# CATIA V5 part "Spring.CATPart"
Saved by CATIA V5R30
Part number: Part1
Bounding box of the stored display mesh (mm): x -50 to 50, y -44.999 to 44.983, z -4.984 to 154.984
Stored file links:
  D:\PROJECTS\CATIA V56R 2020\Resources\Tutorial Files\c19_catia_v5_6r2019_tut\C19_tut_01.CATPart\Spring.CATPart
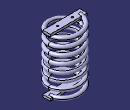
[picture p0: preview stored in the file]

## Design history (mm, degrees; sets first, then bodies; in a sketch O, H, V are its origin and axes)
Body1 (main body)
  Point1: (0, 0, 0)
  Point2: (0, 0, 150)
  Line1: type PtPt, FirstPoint Point2, SecondPoint Point1
  Point3: (40, 0, 0)
  Helix1: Direction Line1, RefPoint Point3, Pitch 20, Height 150, TaperAngle 0, Revolutions 1
  Plane1: type Normal, Curve Helix1, RefPoint vertex of Helix1, Ratio 0
  Sketch1 on Plane1, origin (0, -11.8615, 0.9439), H (1, 0, 0), V (0, 0.0793, 0.9968)
    circle A1 centre (-40, 149.5273) radius 5
    point P1 (-40, 149.5273)
    reference projected point E1 (-40, 149.5273) from vertex of Helix1
    radius A1 = 5
    coincidence: P1 E1
  Rib1: profile Sketch1, centre curve Helix1
  Sketch2 on xy-plane, origin (0, 0, 0), H (1, 0, 0), V (0, 1, 0)
    line L1 (-50, 10) -> (50, 10)
    line L2 (50, 10) -> (50, -10)
    line L3 (50, -10) -> (-50, -10)
    line L4 (-50, -10) -> (-50, 10)
    length L1 = 100
    distance L1 L3 = 20
    horizontal: L1 H, L3 H
    vertical: L2 V, L4 V
    symmetry: L3 L1 H, L2 L4 V
  Pad1: profile Sketch2, direction (0, 0, 1), length 3, mirrored extent
  Sketch3 on start face of Pad1, origin (0, 0, -3), H (1, 0, 0), V (0, -1, 0)
    circle A1 centre (-24.223, 0) radius 2.5
    point P1 (-24.223, 0)
    circle A2 centre (24.223, 0) radius 2.5
    point P2 (24.223, 0)
    radius A2 = 2.5
    coincidence: P1 H, P2 H
    symmetry: A2 A1 V
  Pocket1: profile Sketch3, direction (0, 0, 1), length 3
  Plane2: type Offset, RefPlane xy-plane, Offset 150
  Sketch4 on Plane2, origin (0, 0, 150), H (1, 0, 0), V (0, 1, 0)
    line L1 (-50, 10) -> (50, 10)
    line L2 (50, 10) -> (50, -10)
    line L3 (50, -10) -> (-50, -10)
    line L4 (-50, -10) -> (-50, 10)
    reference projected line E1 (50, -10) -> (50, 10) from edge [face of Pad1 from Sketch2.L2 | end face of Pad1]
    reference projected line E2 (-50, 10) -> (-50, -10) from edge [face of Pad1 from Sketch2.L4 | end face of Pad1]
    reference projected line E3 (-50, -10) -> (50, -10) from edge [face of Pad1 from Sketch2.L3 | end face of Pad1]
    reference projected line E4 (50, 10) -> (-50, 10) from edge [face of Pad1 from Sketch2.L1 | end face of Pad1]
    horizontal: L1 H, L3 H
    vertical: L2 V, L4 V
    coincidence: L2 E1, L4 E2, E3 L3, L1 E4
  Pad2: profile Sketch4, direction (0, 0, 1), length 3, mirrored extent
  Sketch5 on end face of Pad2, origin (0, 0, 153), H (1, 0, 0), V (0, 1, 0)
    circle A1 centre (-20.0406, 0) radius 2.5674
    point P1 (-20.0406, 0)
    circle A2 centre (20.0406, 0) radius 2.5674
    coincidence: P1 H
    symmetry: A1 A2 V
  Pocket2: profile Sketch5, direction (0, 0, -1), through (limit type 6)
